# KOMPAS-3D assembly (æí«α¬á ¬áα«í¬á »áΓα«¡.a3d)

Referenced files in D:\МОДЕЛЬ ТАНКА Т90\ДЕТАЛИ\БАШНЯ\башня сварная\: коробка патрон.m3d
Referenced files in D:\МОДЕЛЬ ТАНКА Т90\ДЕТАЛИ\ОБЩИЕ ДЕТАЛИ\: замки ящиков.m3d
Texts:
  Сборка каробка патрон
